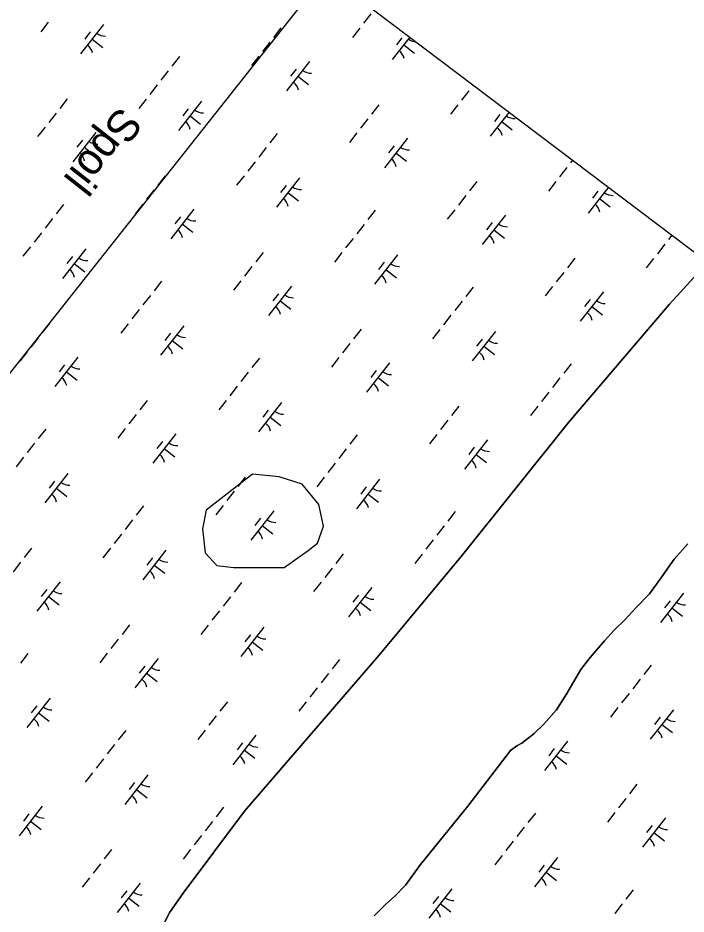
# Model space of a CAD drawing. Extents: x 3896831 to 3918110, y 171006 to 193349.
# Drawn here: x 3913937 to 3914830, y 184635 to 185832 of the extents above; entities that cross this region are included whole.
import ezdxf

# ---------------------------------------------------------------- set-up
doc = ezdxf.new("R2010")
doc.units = 0
for name, color, linetype in [('V-CHAN-SPOL', 7, 'Continuous'), ('V-GRID-FRAM', 7, 'Continuous'), ('V-TOPO-SHOR', 7, 'Continuous'), ('V-UTIL-LINE', 7, 'Continuous'), ('V-WETL-SWMP', 7, 'Continuous')]:
    doc.layers.add(name, color=color, linetype=linetype)

msp = doc.modelspace()

# ---------------------------------------------------------------- linework, layer by layer
at = {"layer": 'V-GRID-FRAM'}
msp.add_lwpolyline([(3916044.9, 184610), (3906752.8, 172754.1), (3900055.1, 177809.8), (3909313.3, 189695.8), (3916044.9, 184610)], dxfattribs=at)
at = {"layer": 'V-TOPO-SHOR'}
for points in [[(3913787.5, 184219.9), (3913880.9, 184342.4), (3913974.4, 184459), (3914047, 184540.6), (3914063, 184549.5), (3914076.9, 184556.2), (3914088.2, 184563.6), (3914099.8, 184572.9), (3914115.4, 184590.6), (3914125.9, 184609), (3914140.3, 184637), (3914158, 184662.8), (3914240.2, 184772.3), (3914419.7, 184980.1), (3914529.9, 185112.3), (3914673.4, 185291.6), (3914808.3, 185449.5), (3914859.3, 185505.8)], [(3914455.4, 184673.5), (3914475.3, 184701.1), (3914538.7, 184779), (3914595.5, 184853.1), (3914604.3, 184859.4), (3914610.8, 184863.1), (3914627.2, 184876.1), (3914639.9, 184887.9), (3914657, 184907.5), (3914671.1, 184929.6), (3914689.8, 184961.3), (3914702.1, 184977.5), (3914721.4, 185000), (3914734.4, 185014.1), (3914749, 185028.5), (3914763.8, 185044.4), (3914781.3, 185062.5), (3914796.5, 185083.5), (3914814.6, 185108.9), (3914832.7, 185129.2)], [(3914413.6, 184632.4), (3914429.2, 184648), (3914440.5, 184658), (3914455.4, 184673.5)]]:
    msp.add_lwpolyline(points, dxfattribs=at)
msp.add_lwpolyline([(3914292.9, 185097.8), (3914325.3, 185120.7), (3914337.7, 185130.3), (3914345.7, 185152.9), (3914339.5, 185181.9), (3914317.3, 185209), (3914286.3, 185218.8), (3914250.7, 185222.6), (3914188.8, 185174.5), (3914183.8, 185149.5), (3914187.6, 185117.5), (3914203.2, 185100.4), (3914225.2, 185097.7), (3914249.6, 185097.9)], close=True, dxfattribs=at)
at = {"layer": 'V-UTIL-LINE'}
msp.add_lwpolyline([(3905549.4, 173652.6), (3906763.3, 174938.4), (3906949.5, 175133), (3906970.6, 175166.8), (3907325.9, 175860.5), (3907748.9, 176681), (3908142.2, 177273.2), (3908679.4, 178098), (3908869.7, 178381.4), (3908937.4, 178537.8), (3909170, 179117.3), (3909533.8, 179633.3), (3910092.1, 180424.3), (3910333.2, 180766.9), (3910760.4, 181291.4), (3910921.1, 181524), (3911225.6, 181951.2), (3911822, 182788.6), (3911961.6, 182987.4), (3912147.7, 183114.3), (3912722.9, 183841.8), (3913090.9, 184307.1), (3913848, 185258.8), (3914364, 185910.1)], dxfattribs=at)
at = {"layer": 'V-WETL-SWMP'}
for p, q in [((3913857.7, 186262.5), (3914859.3, 185505.8)), ((3914409.1, 185837.5), (3914399.2, 185825)), ((3913977.6, 185826.4), (3913967.8, 185813.8)), ((3914051.8, 185823.6), (3914020.9, 185784.3)), ((3914288.8, 185818.8), (3914279, 185806.2)), ((3914394.3, 185818.7), (3914384.4, 185806.1)), ((3914034, 185813.4), (3914026.6, 185804)), ((3914461.1, 185806.6), (3914437.6, 185776.6)), ((3914450.6, 185805.7), (3914443.2, 185796.3)), ((3914036.4, 185803.9), (3914050.5, 185792.8)), ((3914274, 185799.9), (3914264.2, 185787.3)), ((3914453, 185796.2), (3914467.2, 185785.1)), ((3914259.2, 185781), (3914249.3, 185768.4)), ((3914153, 185780.4), (3914143.1, 185767.8)), ((3914327, 185774), (3914296.2, 185734.6)), ((3914138.2, 185761.5), (3914128.3, 185748.9)), ((3914309.2, 185763.8), (3914301.8, 185754.3)), ((3914311.6, 185754.3), (3914325.8, 185743.2)), ((3914123.4, 185742.6), (3914113.5, 185730)), ((3914540, 185734.9), (3914530.1, 185722.3)), ((3914546, 185742.5), (3914544.9, 185741.2)), ((3914003.1, 185723.9), (3913993.2, 185711.3)), ((3914108.6, 185723.8), (3914098.7, 185711.2)), ((3914182.7, 185721), (3914151.9, 185681.7)), ((3914164.9, 185710.8), (3914157.5, 185701.4)), ((3914419.7, 185716.2), (3914409.9, 185703.6)), ((3914525.2, 185716.1), (3914515.3, 185703.5)), ((3913988.3, 185705), (3913978.4, 185692.4)), ((3914167.3, 185701.3), (3914181.4, 185690.2)), ((3914404.9, 185697.3), (3914395.1, 185684.7)), ((3914593.9, 185706.3), (3914568.5, 185674)), ((3914581.5, 185703.1), (3914574.1, 185693.7)), ((3913973.5, 185686.1), (3913963.6, 185673.5)), ((3914583.9, 185693.6), (3914598.1, 185682.5)), ((3914041.3, 185679.1), (3914010.5, 185639.7)), ((3914283.9, 185677.8), (3914274, 185665.2)), ((3914390.1, 185678.4), (3914380.3, 185665.8)), ((3914023.5, 185668.9), (3914016.1, 185659.4)), ((3914458, 185671.4), (3914427.1, 185632)), ((3914440.2, 185661.2), (3914432.8, 185651.7)), ((3914025.9, 185659.4), (3914040.1, 185648.3)), ((3914269.1, 185658.9), (3914259.2, 185646.3)), ((3914442.5, 185651.7), (3914456.7, 185640.6)), ((3914254.3, 185640), (3914244.4, 185627.4)), ((3914678.7, 185642.2), (3914675.9, 185638.6)), ((3914670.9, 185632.3), (3914661.1, 185619.7)), ((3914134, 185621.3), (3914124.2, 185608.7)), ((3914239.5, 185621.1), (3914229.6, 185608.5)), ((3914313.6, 185618.4), (3914282.8, 185579.1)), ((3914550.7, 185613.6), (3914540.8, 185601)), ((3914656.1, 185613.4), (3914646.3, 185600.8)), ((3914119.2, 185602.4), (3914109.3, 185589.8)), ((3914295.8, 185608.2), (3914288.4, 185598.8)), ((3914726.6, 185606), (3914699.4, 185571.4)), ((3914298.2, 185598.7), (3914312.4, 185587.6)), ((3914535.9, 185594.7), (3914526, 185582.1)), ((3914712.5, 185600.5), (3914705.1, 185591.1)), ((3914714.8, 185591), (3914729, 185579.9)), ((3913998.2, 185582.9), (3913988.3, 185570.3)), ((3914104.4, 185583.5), (3914094.5, 185570.9)), ((3914172.2, 185576.5), (3914141.4, 185537.1)), ((3914154.4, 185566.3), (3914147, 185556.8)), ((3914414.8, 185575.2), (3914404.9, 185562.6)), ((3914521.1, 185575.8), (3914511.2, 185563.2)), ((3914588.9, 185568.8), (3914558, 185529.4)), ((3913983.4, 185564), (3913973.5, 185551.4)), ((3914156.8, 185556.8), (3914171, 185545.7)), ((3914400, 185556.3), (3914390.1, 185543.7)), ((3914571.1, 185558.6), (3914563.7, 185549.1)), ((3913968.6, 185545.1), (3913958.7, 185532.5)), ((3914573.4, 185549.1), (3914587.6, 185538)), ((3914811.4, 185542), (3914806.8, 185536)), ((3914385.2, 185537.4), (3914375.3, 185524.8)), ((3914801.9, 185529.7), (3914792, 185517.1)), ((3913953.8, 185526.2), (3913943.9, 185513.6)), ((3914027.9, 185523.5), (3913997, 185484.1)), ((3914264.9, 185518.7), (3914255.1, 185506.1)), ((3914370.4, 185518.5), (3914360.5, 185505.9)), ((3914010.1, 185513.3), (3914002.7, 185503.9)), ((3914444.5, 185515.8), (3914413.7, 185476.4)), ((3914426.7, 185505.6), (3914419.3, 185496.2)), ((3914681.6, 185511), (3914671.7, 185498.4)), ((3914787, 185510.8), (3914777.2, 185498.2)), ((3914859.3, 185505.8), (3914808.3, 185449.5)), ((3914012.5, 185503.8), (3914026.6, 185492.7)), ((3914250.1, 185499.8), (3914240.3, 185487.2)), ((3914429.1, 185496.1), (3914443.3, 185485)), ((3914666.8, 185492.1), (3914656.9, 185479.5)), ((3914129.1, 185480.3), (3914119.2, 185467.7)), ((3914235.3, 185480.9), (3914225.5, 185468.3)), ((3914303.1, 185473.8), (3914272.3, 185434.5)), ((3914545.7, 185472.6), (3914535.9, 185460)), ((3914652, 185473.2), (3914642.1, 185460.6)), ((3914114.3, 185461.4), (3914104.4, 185448.8)), ((3914285.4, 185463.7), (3914278, 185454.2)), ((3914719.8, 185466.1), (3914688.9, 185426.8)), ((3914287.7, 185454.2), (3914301.9, 185443.1)), ((3914530.9, 185453.7), (3914521.1, 185441.1)), ((3914808.3, 185449.5), (3914673.4, 185291.6)), ((3914702, 185456), (3914694.6, 185446.5)), ((3914704.4, 185446.5), (3914718.5, 185435.4)), ((3914099.5, 185442.5), (3914089.6, 185429.9)), ((3914516.1, 185434.8), (3914506.3, 185422.2)), ((3913979.2, 185423.8), (3913969.3, 185411.2)), ((3914084.7, 185423.6), (3914074.8, 185411)), ((3914158.8, 185420.9), (3914128, 185381.5)), ((3914141, 185410.7), (3914133.6, 185401.3)), ((3914395.9, 185416.1), (3914386, 185403.5)), ((3914501.3, 185415.9), (3914491.5, 185403.3)), ((3914575.5, 185413.2), (3914544.6, 185373.8)), ((3913964.4, 185404.9), (3913954.5, 185392.3)), ((3914143.4, 185401.2), (3914157.6, 185390.1)), ((3914557.7, 185403), (3914550.3, 185393.6)), ((3913949.6, 185386), (3913939.7, 185373.4)), ((3914381.1, 185397.2), (3914371.2, 185384.6)), ((3914560, 185393.5), (3914574.2, 185382.4)), ((3914017.4, 185378.9), (3913986.6, 185339.6)), ((3914260, 185377.7), (3914250.1, 185365.1)), ((3914366.2, 185378.3), (3914356.4, 185365.7)), ((3913999.6, 185368.7), (3913992.2, 185359.3)), ((3914434.1, 185371.2), (3914403.2, 185331.9)), ((3914676.7, 185370), (3914666.8, 185357.4)), ((3914002, 185359.3), (3914016.2, 185348.2)), ((3914245.2, 185358.8), (3914235.3, 185346.2)), ((3914416.3, 185361), (3914408.9, 185351.6)), ((3914418.6, 185351.6), (3914432.8, 185340.5)), ((3914661.8, 185351.1), (3914652, 185338.5)), ((3914230.4, 185339.9), (3914220.5, 185327.3)), ((3914647, 185332.2), (3914637.2, 185319.6)), ((3914110.1, 185321.1), (3914100.3, 185308.6)), ((3914215.6, 185321), (3914205.7, 185308.4)), ((3914289.7, 185318.3), (3914258.9, 185278.9)), ((3914095.3, 185302.3), (3914085.5, 185289.7)), ((3914271.9, 185308.1), (3914264.5, 185298.6)), ((3914526.8, 185313.4), (3914516.9, 185300.9)), ((3914632.2, 185313.3), (3914622.4, 185300.7)), ((3914274.3, 185298.6), (3914288.5, 185287.5)), ((3914512, 185294.6), (3914502.1, 185282)), ((3914673.4, 185291.6), (3914529.9, 185112.3)), ((3913974.3, 185282.8), (3913964.4, 185270.2)), ((3914080.5, 185283.4), (3914070.7, 185270.8)), ((3914148.3, 185276.3), (3914117.5, 185237)), ((3914130.5, 185266.1), (3914123.1, 185256.7)), ((3914390.9, 185275.1), (3914381.1, 185262.5)), ((3914497.2, 185275.7), (3914487.3, 185263.1)), ((3914565, 185268.6), (3914534.1, 185229.3)), ((3913959.5, 185263.9), (3913949.6, 185251.3)), ((3914132.9, 185256.7), (3914147.1, 185245.6)), ((3914376.1, 185256.2), (3914366.3, 185243.6)), ((3914547.2, 185258.4), (3914539.8, 185249)), ((3913944.7, 185245), (3913934.8, 185232.4)), ((3914549.6, 185249), (3914563.7, 185237.9)), ((3914361.3, 185237.3), (3914351.4, 185224.7)), ((3914004, 185223.4), (3913973.2, 185184)), ((3914241.1, 185218.5), (3914231.2, 185205.9)), ((3914346.5, 185218.4), (3914336.6, 185205.8)), ((3913986.2, 185213.2), (3913978.8, 185203.7)), ((3914234.1, 185209.7), (3914231.2, 185205.9)), ((3914420.6, 185215.7), (3914389.8, 185176.3)), ((3913988.6, 185203.7), (3914002.8, 185192.6)), ((3914226.2, 185199.6), (3914216.4, 185187.1)), ((3914226.2, 185199.6), (3914216.4, 185187.1)), ((3914402.9, 185205.5), (3914395.5, 185196)), ((3914405.2, 185196), (3914419.4, 185184.9)), ((3914105.2, 185180.2), (3914095.3, 185167.6)), ((3914211.4, 185180.8), (3914201.6, 185168.2)), ((3914211.4, 185180.8), (3914201.6, 185168.2)), ((3914279.3, 185173.7), (3914248.4, 185134.4)), ((3914279.3, 185173.7), (3914248.4, 185134.4)), ((3914521.8, 185172.5), (3914512, 185159.9)), ((3914090.4, 185161.3), (3914080.5, 185148.7)), ((3914261.5, 185163.5), (3914254.1, 185154.1)), ((3914261.5, 185163.5), (3914254.1, 185154.1)), ((3914263.8, 185154), (3914278, 185142.9)), ((3914263.8, 185154), (3914278, 185142.9)), ((3914507, 185153.6), (3914497.2, 185141)), ((3914075.6, 185142.4), (3914065.7, 185129.8)), ((3914492.2, 185134.7), (3914482.4, 185122.1)), ((3913955.3, 185123.6), (3913945.5, 185111)), ((3914060.8, 185123.5), (3914050.9, 185110.9)), ((3914832.7, 185129.2), (3914814.6, 185108.9)), ((3914134.9, 185120.8), (3914104.1, 185081.4)), ((3914117.1, 185110.6), (3914109.7, 185101.1)), ((3914372, 185115.9), (3914362.1, 185103.3)), ((3914529.9, 185112.3), (3914419.7, 184980.1)), ((3914477.4, 185115.8), (3914467.6, 185103.2)), ((3913940.5, 185104.7), (3913930.7, 185092.1)), ((3914119.5, 185101.1), (3914133.7, 185090)), ((3914814.6, 185108.9), (3914796.5, 185083.5)), ((3914357.2, 185097), (3914347.3, 185084.4)), ((3913993.5, 185078.8), (3913962.7, 185039.5)), ((3914236.1, 185077.6), (3914226.3, 185065)), ((3914342.4, 185078.2), (3914332.5, 185065.6)), ((3914796.5, 185083.5), (3914781.3, 185062.5)), ((3913975.7, 185068.6), (3913968.3, 185059.2)), ((3914410.2, 185071.1), (3914379.3, 185031.8)), ((3914781.3, 185062.5), (3914763.8, 185044.4)), ((3914826.8, 185063.4), (3914796, 185024.1)), ((3913978.1, 185059.1), (3913992.3, 185048)), ((3914221.3, 185058.7), (3914211.4, 185046.1)), ((3914392.4, 185060.9), (3914385, 185051.5)), ((3914394.8, 185051.4), (3914408.9, 185040.3)), ((3914809, 185053.2), (3914801.6, 185043.8)), ((3914206.5, 185039.8), (3914196.6, 185027.2)), ((3914763.8, 185044.4), (3914749, 185028.5)), ((3914811.4, 185043.7), (3914825.6, 185032.6)), ((3914749, 185028.5), (3914734.4, 185014.1)), ((3914086.2, 185021), (3914076.4, 185008.4)), ((3914191.7, 185020.9), (3914181.8, 185008.3)), ((3914265.8, 185018.2), (3914235, 184978.8)), ((3914248, 185008), (3914240.6, 184998.5)), ((3914734.4, 185014.1), (3914721.4, 185000)), ((3914071.4, 185002.1), (3914061.6, 184989.5)), ((3914250.4, 184998.5), (3914264.6, 184987.4)), ((3914721.4, 185000), (3914702.1, 184977.5)), ((3913950.4, 184982.7), (3913940.5, 184970.1)), ((3914056.6, 184983.2), (3914046.8, 184970.6)), ((3914419.7, 184980.1), (3914240.2, 184772.3)), ((3914124.5, 184976.2), (3914093.6, 184936.9)), ((3914367, 184975), (3914357.2, 184962.4)), ((3914702.1, 184977.5), (3914689.8, 184961.3)), ((3914783.7, 184967.3), (3914773.8, 184954.7)), ((3914106.7, 184966), (3914099.3, 184956.6)), ((3914109, 184956.5), (3914123.2, 184945.4)), ((3914352.2, 184956.1), (3914342.4, 184943.5)), ((3914689.8, 184961.3), (3914671.1, 184929.6)), ((3914768.9, 184948.4), (3914759, 184935.8)), ((3914337.4, 184937.2), (3914327.6, 184924.6)), ((3913980.1, 184923.2), (3913949.3, 184883.9)), ((3914671.1, 184929.6), (3914657, 184907.5)), ((3914754.1, 184929.5), (3914744.2, 184916.9)), ((3913962.3, 184913.1), (3913954.9, 184903.6)), ((3914217.2, 184918.4), (3914207.3, 184905.8)), ((3914322.6, 184918.3), (3914312.8, 184905.7)), ((3914657, 184907.5), (3914639.9, 184887.9)), ((3914739.3, 184910.6), (3914729.4, 184898)), ((3914813.4, 184907.8), (3914782.6, 184868.5)), ((3913964.7, 184903.6), (3913978.9, 184892.5)), ((3914202.4, 184899.5), (3914192.5, 184886.9)), ((3914795.6, 184897.7), (3914788.2, 184888.2)), ((3914639.9, 184887.9), (3914627.2, 184876.1)), ((3914798, 184888.2), (3914812.1, 184877.1)), ((3914081.3, 184880), (3914071.4, 184867.4)), ((3914187.6, 184880.6), (3914177.7, 184868)), ((3914255.4, 184873.6), (3914224.5, 184834.2)), ((3914627.2, 184876.1), (3914610.8, 184863.1)), ((3914066.5, 184861.2), (3914056.6, 184848.6)), ((3914237.6, 184863.4), (3914230.2, 184854)), ((3914604.3, 184859.4), (3914595.5, 184853.1)), ((3914610.8, 184863.1), (3914604.3, 184859.4)), ((3914672, 184865.9), (3914641.2, 184826.5)), ((3914239.9, 184853.9), (3914254.1, 184842.8)), ((3914595.5, 184853.1), (3914538.7, 184779)), ((3914654.2, 184855.7), (3914646.8, 184846.3)), ((3914051.7, 184842.3), (3914041.8, 184829.7)), ((3914656.6, 184846.2), (3914670.8, 184835.1)), ((3914036.9, 184823.4), (3914027, 184810.8)), ((3914111, 184820.6), (3914080.2, 184781.3)), ((3914093.2, 184810.4), (3914085.8, 184801)), ((3914095.6, 184801), (3914109.8, 184789.9)), ((3914764.7, 184808.1), (3914754.9, 184795.5)), ((3914749.9, 184789.2), (3914740.1, 184776.6)), ((3913969.6, 184778.7), (3913938.8, 184739.3)), ((3914212.2, 184777.4), (3914202.4, 184764.8)), ((3914538.7, 184779), (3914475.3, 184701.1)), ((3913951.9, 184768.5), (3913944.5, 184759)), ((3914240.2, 184772.3), (3914158, 184662.8)), ((3914628.9, 184769.7), (3914619, 184757.1)), ((3914735.1, 184770.3), (3914725.2, 184757.7)), ((3914802.9, 184763.3), (3914772.1, 184723.9)), ((3913954.2, 184759), (3913968.4, 184747.9)), ((3914197.4, 184758.5), (3914187.6, 184746)), ((3914614.1, 184750.8), (3914604.2, 184738.3)), ((3914785.1, 184753.1), (3914777.7, 184743.6)), ((3914182.6, 184739.7), (3914172.8, 184727.1)), ((3914787.5, 184743.6), (3914801.7, 184732.5)), ((3914599.3, 184732), (3914589.4, 184719.4)), ((3914062.4, 184720.9), (3914052.5, 184708.3)), ((3914167.8, 184720.8), (3914158, 184708.2)), ((3914584.5, 184713.1), (3914574.6, 184700.5)), ((3914658.6, 184710.3), (3914627.8, 184671)), ((3914047.6, 184702), (3914037.7, 184689.4)), ((3914475.3, 184701.1), (3914455.4, 184673.5)), ((3914640.8, 184700.1), (3914633.4, 184690.7)), ((3914032.7, 184683.1), (3914022.9, 184670.5)), ((3914643.2, 184690.7), (3914657.3, 184679.5)), ((3914100.6, 184676.1), (3914069.7, 184636.7)), ((3914455.4, 184673.5), (3914440.5, 184658)), ((3914517.2, 184668.4), (3914486.4, 184629)), ((3914759.8, 184667.1), (3914749.9, 184654.5)), ((3914082.8, 184665.9), (3914075.4, 184656.4)), ((3914085.1, 184656.4), (3914099.3, 184645.3)), ((3914158, 184662.8), (3914140.3, 184637)), ((3914440.5, 184658), (3914429.2, 184648)), ((3914499.4, 184658.2), (3914492, 184648.7)), ((3914429.2, 184648), (3914413.6, 184632.4)), ((3914501.8, 184648.7), (3914516, 184637.6)), ((3914745, 184648.2), (3914735.1, 184635.6)), ((3914140.3, 184637), (3914125.9, 184609))]:
    msp.add_line(p, q, dxfattribs=at)
msp.add_lwpolyline([(3914292.9, 185097.8), (3914325.3, 185120.7), (3914337.7, 185130.3), (3914345.7, 185152.9), (3914339.5, 185181.9), (3914317.3, 185209), (3914286.3, 185218.8), (3914250.7, 185222.6), (3914188.8, 185174.5), (3914183.8, 185149.5), (3914187.6, 185117.5), (3914203.2, 185100.4), (3914225.2, 185097.7), (3914249.6, 185097.9)], close=True, dxfattribs=at)
for centre, start, end in [((3914053.6, 185825.5), 231.1403, 272.6839), ((3914019.5, 185782.1), 11.1403, 52.6839), ((3914470.2, 185817.8), 231.1403, 267.8769), ((3914436.1, 185774.4), 11.1403, 52.6839), ((3914328.8, 185775.9), 231.1403, 272.6839), ((3914294.8, 185732.4), 11.1403, 52.6839), ((3914184.5, 185722.9), 231.1403, 272.6839), ((3914601.1, 185715.2), 231.1403, 272.6839), ((3914150.4, 185679.5), 11.1403, 52.6839), ((3914567.1, 185671.8), 11.1403, 52.6839), ((3914043.1, 185681), 231.1403, 272.6839), ((3914009, 185637.5), 11.1403, 52.6839), ((3914459.8, 185673.3), 231.1403, 272.6839), ((3914425.7, 185629.8), 11.1403, 52.6839), ((3914315.4, 185620.3), 231.1403, 272.6839), ((3914281.3, 185576.8), 11.1403, 52.6839), ((3914732.1, 185612.6), 231.1403, 272.6839), ((3914698, 185569.1), 11.1403, 52.6839), ((3914174, 185578.4), 231.1403, 272.6839), ((3914590.7, 185570.7), 231.1403, 272.6839), ((3914140, 185534.9), 11.1403, 52.6839), ((3914556.6, 185527.2), 11.1403, 52.6839), ((3914029.7, 185525.4), 231.1403, 272.6839), ((3913995.6, 185481.9), 11.1403, 52.6839), ((3914446.3, 185517.7), 231.1403, 272.6839), ((3914412.3, 185474.2), 11.1403, 52.6839), ((3914304.9, 185475.8), 231.1403, 272.6839), ((3914270.9, 185432.3), 11.1403, 52.6839), ((3914721.6, 185468.1), 231.1403, 272.6839), ((3914687.5, 185424.6), 11.1403, 52.6839), ((3914160.6, 185422.8), 231.1403, 272.6839), ((3914577.3, 185415.1), 231.1403, 272.6839), ((3914126.5, 185379.3), 11.1403, 52.6839), ((3914543.2, 185371.6), 11.1403, 52.6839), ((3914019.2, 185380.9), 231.1403, 272.6839), ((3913985.1, 185337.4), 11.1403, 52.6839), ((3914435.9, 185373.2), 231.1403, 272.6839), ((3914401.8, 185329.7), 11.1403, 52.6839), ((3914291.5, 185320.2), 231.1403, 272.6839), ((3914257.5, 185276.7), 11.1403, 52.6839), ((3914150.1, 185278.2), 231.1403, 272.6839), ((3914566.8, 185270.5), 231.1403, 272.6839), ((3914116.1, 185234.8), 11.1403, 52.6839), ((3914532.7, 185227.1), 11.1403, 52.6839), ((3914005.8, 185225.3), 231.1403, 272.6839), ((3913971.7, 185181.8), 11.1403, 52.6839), ((3914422.5, 185217.6), 231.1403, 272.6839), ((3914388.4, 185174.1), 11.1403, 52.6839), ((3914281.1, 185175.6), 231.1403, 272.6839), ((3914281.1, 185175.6), 231.1403, 272.6839), ((3914247, 185132.2), 11.1403, 52.6839), ((3914247, 185132.2), 11.1403, 52.6839), ((3914136.7, 185122.7), 231.1403, 272.6839), ((3914102.7, 185079.2), 11.1403, 52.6839), ((3913995.3, 185080.7), 231.1403, 272.6839), ((3913961.3, 185037.3), 11.1403, 52.6839), ((3914412, 185073), 231.1403, 272.6839), ((3914828.6, 185065.3), 231.1403, 272.6839), ((3914377.9, 185029.6), 11.1403, 52.6839), ((3914794.5, 185021.9), 11.1403, 52.6839), ((3914267.6, 185020.1), 231.1403, 272.6839), ((3914233.6, 184976.6), 11.1403, 52.6839), ((3914126.3, 184978.1), 231.1403, 272.6839), ((3914092.2, 184934.6), 11.1403, 52.6839), ((3913981.9, 184925.2), 231.1403, 272.6839), ((3913947.8, 184881.7), 11.1403, 52.6839), ((3914815.2, 184909.8), 231.1403, 272.6839), ((3914781.1, 184866.3), 11.1403, 52.6839), ((3914257.2, 184875.5), 231.1403, 272.6839), ((3914673.8, 184867.8), 231.1403, 272.6839), ((3914223.1, 184832), 11.1403, 52.6839), ((3914639.7, 184824.3), 11.1403, 52.6839), ((3914112.8, 184822.6), 231.1403, 272.6839), ((3914078.8, 184779.1), 11.1403, 52.6839), ((3913971.5, 184780.6), 231.1403, 272.6839), ((3913937.4, 184737.1), 11.1403, 52.6839), ((3914804.7, 184765.2), 231.1403, 272.6839), ((3914770.7, 184721.7), 11.1403, 52.6839), ((3914660.4, 184712.2), 231.1403, 272.6839), ((3914626.3, 184668.8), 11.1403, 52.6839), ((3914102.4, 184678), 231.1403, 272.6839), ((3914519, 184670.3), 231.1403, 272.6839), ((3914068.3, 184634.5), 11.1403, 52.6839), ((3914484.9, 184626.8), 11.1403, 52.6839)]:
    msp.add_arc(centre, 17.6, start, end, dxfattribs=at)

# ---------------------------------------------------------------- texts
at = {"layer": 'V-CHAN-SPOL'}
msp.add_text('Spoil', height=42, rotation=231.9086, dxfattribs=at).set_placement((3914073.4, 185715.8))

doc.saveas('drawing.dxf')
